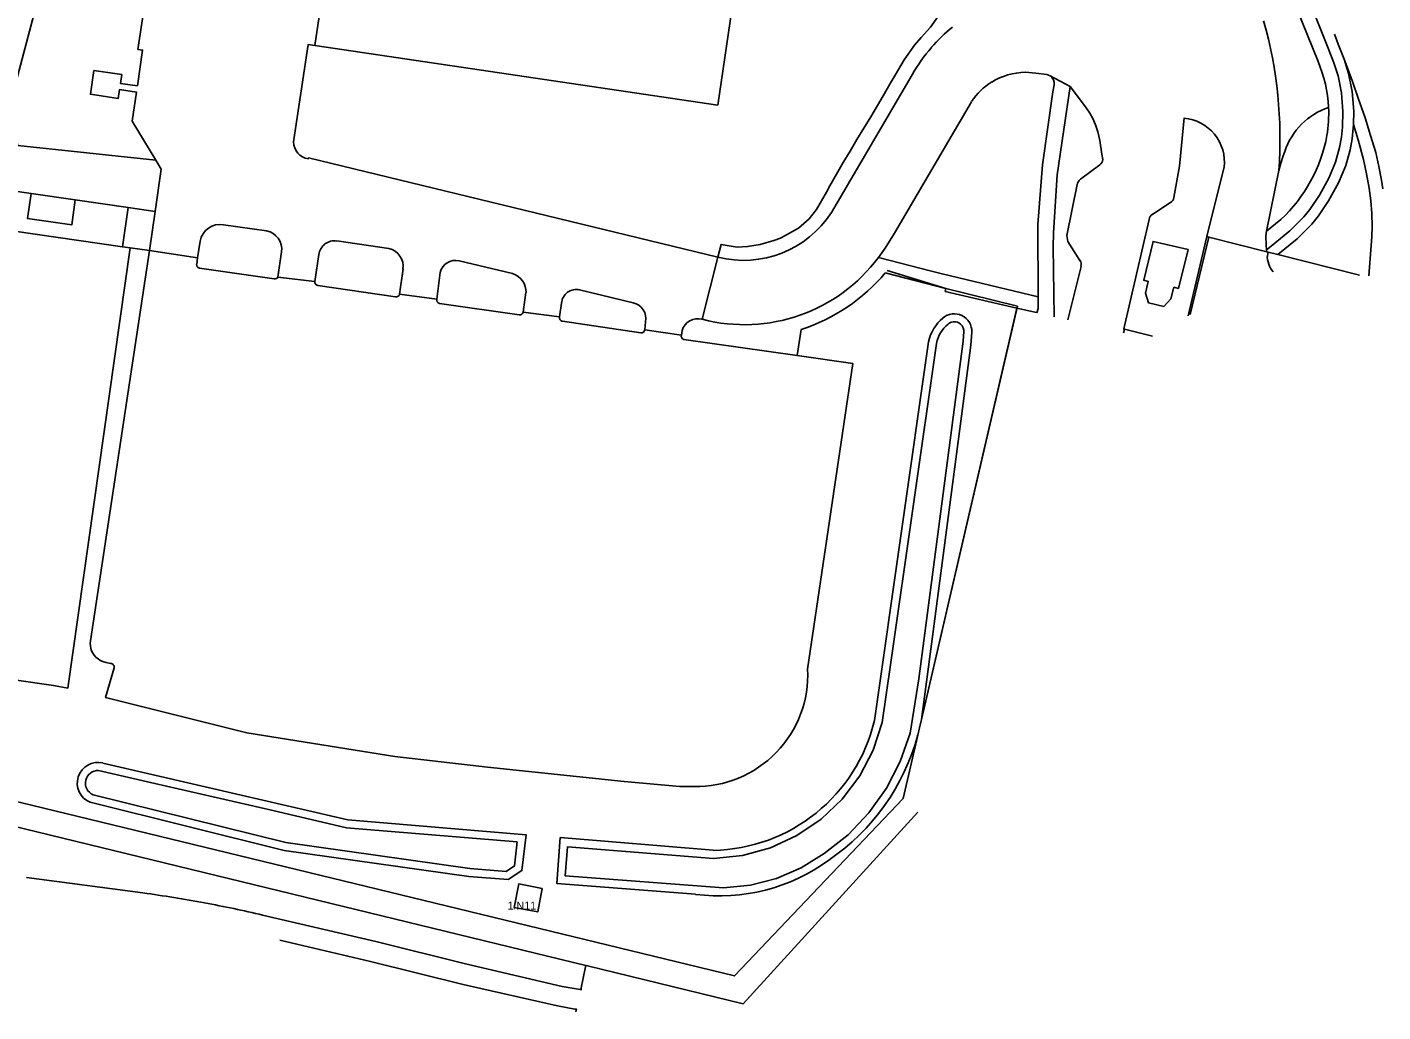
# Model space of a CAD drawing. Extents: x 163046 to 165074, y 382019 to 382874.
# Drawn here: x 164887 to 165056.4, y 382019.4 to 382142.4 of the extents above; entities that cross this region are included whole.
import ezdxf

# ---------------------------------------------------------------- set-up
doc = ezdxf.new("R2010")
doc.units = 0
for name, color, linetype in [('IMGEO_Berm_groen', 7, 'Continuous'), ('IMGEO_Erf', 7, 'Continuous'), ('IMGEO_Fietspad_gesloten', 7, 'Continuous'), ('IMGEO_Fietspad_open', 7, 'Continuous'), ('IMGEO_Groenvoorziening', 7, 'Continuous'), ('IMGEO_Hek', 7, 'Continuous'), ('IMGEO_Pand', 7, 'Continuous'), ('IMGEO_Pand_nummerreeks', 7, 'Continuous'), ('IMGEO_Parkeervlak_gesloten', 7, 'Continuous'), ('IMGEO_Parkeervlak_open', 7, 'Continuous'), ('IMGEO_Rijbaan_lokaal_gesloten', 7, 'Continuous'), ('IMGEO_Rijbaan_lokaal_open', 7, 'Continuous'), ('IMGEO_Voetpad_open', 7, 'Continuous'), ('IMGEO_Waterloop', 7, 'Continuous')]:
    doc.layers.add(name, color=color, linetype=linetype)

msp = doc.modelspace()

# ---------------------------------------------------------------- linework, layer by layer
at = {"layer": 'IMGEO_Berm_groen'}
msp.add_lwpolyline([(165043.31, 382114.01), (165053.48, 382111.43)], dxfattribs=at)
at = {"layer": 'IMGEO_Erf'}
msp.add_lwpolyline([(164899.25, 382173.36), (164895.44, 382168.42), (164892.95, 382163.15), (164891.24, 382156.72), (164887.33, 382141.95), (164884.69, 382132.02), (164885.86, 382127.64)], dxfattribs=at)
at = {"layer": 'IMGEO_Fietspad_gesloten'}
for points in [[(164901.48, 382034.26), (164886.96, 382036.16)], [(164956.22, 382022.18), (164956.12, 382022.19), (164953.88, 382022.57), (164941.81, 382025.37), (164930.58, 382028.18), (164916.45, 382031.48)], [(164918.61, 382028.36), (164929.91, 382025.67), (164941.52, 382022.81), (164953.3, 382020.13), (164955.47, 382019.72), (164955.65, 382019.7)], [(164956.32, 382022.17), (164956.22, 382022.18)], [(164955.72, 382019.69), (164955.65, 382019.7)]]:
    msp.add_lwpolyline(points, dxfattribs=at)
for centre, radius, start, end in [((164878.38, 381867.91), 167.94, 79.4249, 82.0936), ((164878.35, 381867.42), 168.43, 76.9252, 79.4441)]:
    msp.add_arc(centre, radius, start, end, dxfattribs=at)
at = {"layer": 'IMGEO_Fietspad_open'}
for points in [[(165041.88, 382114.6), (165042.46, 382115.06), (165044.81, 382116.97), (165046.53, 382118.72), (165047.31, 382119.67), (165048.49, 382121.44), (165049.66, 382123.56), (165050.51, 382125.59), (165051.01, 382127.42), (165051.24, 382128.68), (165051.37, 382129.96), (165051.43, 382131.91), (165051.26, 382134.23), (165050.83, 382136.34), (165050.31, 382138), (165049.6, 382139.82), (165045.28, 382150.62)], [(165043.62, 382149.82), (165048.32, 382138.13)], [(165015.34, 382135.25), (165015.2, 382134.35), (165013.87, 382125.23), (165013.3, 382117.77), (165013.35, 382108.72)], [(165015.34, 382106.26), (165015.24, 382115), (165015.25, 382116.74), (165015.73, 382124), (165017.36, 382135.02)], [(165043.68, 382118.41), (165041.88, 382116.94)], [(165013.2, 382106.76), (165013.36, 382107.28), (165013.35, 382108.72)]]:
    msp.add_lwpolyline(points, dxfattribs=at)
for centre, radius, start, end in [((165033.03, 382131.63), 16.62, 2.75, 23.0338), ((165014.19, 382135.38), 1.16, 353.1527, 56.2591), ((165032.96, 382131.62), 16.69, 350.5763, 2.7535), ((165030.58, 382132.41), 19.17, 313.1209, 349.4285)]:
    msp.add_arc(centre, radius, start, end, dxfattribs=at)
at = {"layer": 'IMGEO_Groenvoorziening'}
for points in [[(165005.06, 382104.33), (165004.93, 382102.71), (165000, 382065.32), (164998.76, 382055.9)], [(164992.89, 382055.79), (164999.66, 382103.13)], [(164896.49, 382050.48), (164927.09, 382043.38), (164949.37, 382041.52), (164948.84, 382037.04), (164947.13, 382035.91), (164942.23, 382036.3), (164919.16, 382039.55), (164894.91, 382045.57)], [(164970.53, 382034.07), (164953.19, 382035.44), (164953.64, 382041.16), (164972.76, 382039.57)]]:
    msp.add_lwpolyline(points, dxfattribs=at)
for centre, radius, start, end in [((165004.77, 382102.07), 5.22, 129.5656, 168.2281), ((165002.87, 382104.43), 2.19, 357.3821, 130.7763), ((164972.36, 382060.66), 21.1, 271.0694, 346.6392), ((164971.63, 382061.19), 27.64, 304.3023, 344.8961), ((164895.88, 382047.97), 2.59, 76.4768, 248.0161), ((164973.54, 382056.96), 23.09, 262.5139, 306.2932)]:
    msp.add_arc(centre, radius, start, end, dxfattribs=at)
at = {"layer": 'IMGEO_Hek'}
for points in [[(164548.87, 382121.27), (164552, 382120.52), (164561.05, 382119.57), (164562.96, 382119.37), (164565.36, 382119.11), (164598.77, 382115.22), (164621.38, 382109.91), (164648.88, 382103.16), (164975.4, 382023.88), (164996.47, 382046.06), (164998.31, 382053.98)], [(165041.9, 382114.37), (165034.66, 382116.21), (165032.36, 382106.54)], [(165042.1, 382114.32), (165041.9, 382114.37)], [(165043.31, 382114.01), (165042.1, 382114.32)], [(164957.04, 382025.14), (164956.85, 382025.19), (164602.85, 382111.38), (164599.99, 382112.07), (164598.73, 382112.35), (164598.36, 382112.35)], [(165010.75, 382107.57), (165001.81, 382109.8), (164994.49, 382112.04)], [(164998.76, 382055.9), (165010.75, 382107.57)], [(164998.31, 382053.98), (164998.52, 382054.86), (164998.76, 382055.9)], [(164998.3, 382044.35), (164976.47, 382020.39)]]:
    msp.add_lwpolyline(points, dxfattribs=at)
at = {"layer": 'IMGEO_Pand'}
for points in [[(164922.97, 382140.15), (164973.31, 382132.7), (164976.41, 382153.71)], [(164923.75, 382145.43), (164922.97, 382140.15)], [(165032.08, 382114.65), (165030.87, 382109.8), (165030.31, 382109.94), (165029.93, 382108.47), (165029.04, 382107.55), (165027.15, 382107.97), (165026.76, 382109.19), (165027.11, 382110.67), (165026.53, 382110.81), (165027.71, 382115.66), (165032.08, 382114.65)], [(164951.39, 382034.81), (164950.83, 382031.87), (164947.89, 382032.43), (164948.45, 382035.37), (164951.39, 382034.81)]]:
    msp.add_lwpolyline(points, dxfattribs=at)
at = {"layer": 'IMGEO_Parkeervlak_gesloten'}
msp.add_lwpolyline([(165044.16, 382126.92), (165043.96, 382126.35), (165043.67, 382125.44), (165043.41, 382124.53)], dxfattribs=at)
msp.add_arc((165052.53, 382124.07), 8.84, 109.1598, 161.2369, dxfattribs=at)
at = {"layer": 'IMGEO_Parkeervlak_open'}
for points in [[(164898.94, 382115), (164879.93, 382117.75)], [(164899.91, 382114.86), (164892.11, 382059.85), (164890.33, 382060.16), (164871.21, 382062.93)], [(164902.3, 382114.51), (164894.95, 382065.75)], [(164908.32, 382113.61), (164908.21, 382112.83)], [(164908.58, 382112.33), (164917.9, 382110.97)], [(164923.35, 382110.17), (164933.06, 382108.73)], [(164938.55, 382107.92), (164948.52, 382106.49)], [(164953.92, 382105.68), (164963.71, 382104.24)], [(164984.54, 382062.19), (164990.2, 382100.39), (164983.25, 382101.39)], [(164896.9, 382063.03), (164897.45, 382062.92)], [(164897.89, 382062.36), (164896.83, 382058.66), (164914.49, 382054.25), (164932.97, 382051.3), (164944.56, 382049.97), (164961.62, 382048.15), (164968.57, 382047.56), (164970.34, 382047.53)]]:
    msp.add_lwpolyline(points, dxfattribs=at)
for centre, radius, start, end in [((164908.64, 382112.77), 0.438, 171.3193, 261.6835), ((164917.97, 382111.37), 0.405, 259.0794, 335.6832), ((164923.4, 382110.6), 0.427, 169.758, 263.2449), ((164933.11, 382109.2), 0.473, 263.3412, 344.0389), ((164938.64, 382108.36), 0.447, 170.5053, 258.3116), ((164948.59, 382106.89), 0.401, 259.9073, 350.3244), ((164954, 382106.15), 0.475, 170.1555, 260.3452), ((164963.76, 382104.67), 0.431, 263.5405, 353.3973), ((164897.15, 382065.36), 2.24, 169.9106, 235.5071), ((164897.44, 382065.46), 2.49, 231.4441, 257.48), ((164897.42, 382062.45), 0.474, 349.5505, 86.6098), ((164970.57, 382061.52), 13.99, 269.0693, 2.7649)]:
    msp.add_arc(centre, radius, start, end, dxfattribs=at)
at = {"layer": 'IMGEO_Rijbaan_lokaal_gesloten'}
for points in [[(164997.6, 382136.5), (164987.51, 382119.26)], [(165011.73, 382136.8), (165013.05, 382136.69), (165014.44, 382136.52), (165014.83, 382136.35)], [(165017.36, 382135.02), (165014.83, 382136.35)], [(165021.41, 382125.9), (165021.32, 382126.55), (165021.07, 382128.28), (165020.82, 382129.36), (165020.51, 382130.25), (165020.17, 382131.02), (165019.79, 382131.71), (165019.36, 382132.37), (165018.89, 382133), (165017.36, 382135.02)], [(164993.4, 382113.66), (164994.22, 382114.81), (164995.4, 382116.69), (165005.03, 382133.13)], [(165031.58, 382131.09), (165031.01, 382125.09), (165030.31, 382121.14)], [(164885.86, 382127.64), (164903.11, 382125.8)], [(164903.11, 382125.8), (164903.79, 382124.68), (164903.02, 382119.41)], [(165018.64, 382123.43), (165021.04, 382125.24)], [(165034.44, 382116.27), (165034.65, 382117.16), (165036.6, 382124.93)], [(165041.88, 382116.94), (165043.41, 382124.53)], [(164882.62, 382122.36), (164887.54, 382121.65)], [(165018.57, 382113.3), (165017.07, 382115.64), (165016.92, 382116.41), (165018.22, 382122.77)], [(164887.54, 382121.65), (164893.04, 382120.85)], [(164893.04, 382120.85), (164899.65, 382119.9)], [(165029.89, 382120.52), (165028.19, 382119.41), (165027.63, 382119.05)], [(164899.65, 382119.9), (164903.02, 382119.41)], [(165027.2, 382118.42), (165024.04, 382104.72), (165024.12, 382104.7)], [(165041.88, 382116.94), (165041.8, 382116.35), (165041.82, 382115.21), (165041.88, 382114.6)], [(165034.44, 382116.27), (165032.08, 382106.38)], [(165041.9, 382114.37), (165034.66, 382116.21), (165034.44, 382116.27)], [(164973.33, 382113.68), (164971.38, 382105.93)], [(165041.88, 382114.6), (165041.9, 382114.37)], [(165042.1, 382114.32), (165041.9, 382114.37)], [(165042.71, 382111.85), (165042.54, 382112.08), (165042.39, 382112.32), (165042.26, 382112.57), (165042.15, 382112.84), (165042.07, 382113.11), (165042.01, 382113.39), (165041.97, 382113.67), (165042.1, 382114.32)], [(165017.06, 382105.85), (165018.7, 382112.55)], [(165024.12, 382104.7), (165024, 382104.22)]]:
    msp.add_lwpolyline(points, dxfattribs=at)
for centre, radius, start, end in [((165015.61, 382126.39), 20.65, 128.9397, 139.1131), ((164990.66, 382128.62), 52.9, 355.5693, 16.0146), ((165015.7, 382126.31), 20.76, 139.1141, 150.6292), ((165011.79, 382128.72), 8.08, 121.7268, 146.8426), ((165011.93, 382128.25), 8.55, 91.3486, 120.8889), ((165031.05, 382125.53), 5.58, 353.7795, 84.4866), ((165020.51, 382125.97), 0.906, 305.9775, 355.414), ((165019.34, 382122.52), 1.15, 127.5782, 167.4794), ((165029.48, 382121.25), 0.837, 299.2947, 352.4764), ((164976.5, 382126.47), 13.17, 256.0936, 326.8054), ((165028.17, 382118.22), 0.992, 123.065, 168.3048), ((164976.64, 382126.18), 20.92, 255.4419, 323.2431), ((165017.7, 382112.78), 1.02, 347.2663, 31.0632)]:
    msp.add_arc(centre, radius, start, end, dxfattribs=at)
at = {"layer": 'IMGEO_Rijbaan_lokaal_open'}
for points in [[(164903.4, 382158.01), (164903.55, 382159.66), (164892.91, 382161.18), (164890.74, 382146.43), (164901.63, 382144.87), (164900.87, 382139.65), (164901.46, 382139.57), (164900.81, 382135.11), (164898.68, 382135.42), (164898.84, 382136.51), (164895.38, 382137.02), (164894.94, 382134.05), (164898.4, 382133.54), (164898.56, 382134.63), (164900.69, 382134.32), (164900.16, 382130.69), (164903.11, 382125.8)], [(164920.32, 382128.1), (164922.13, 382140.26), (164922.97, 382140.15)], [(164973.33, 382113.68), (164922.16, 382126.1), (164922.13, 382125.97)], [(164903.02, 382119.41), (164902.3, 382114.51)], [(164911.57, 382117.74), (164916.93, 382116.98)], [(164908.32, 382113.61), (164908.64, 382115.69)], [(164925.71, 382115.72), (164932.23, 382114.78)], [(164902.3, 382114.51), (164908.32, 382113.61)], [(164918.8, 382114.35), (164918.34, 382111.21)], [(164922.98, 382110.67), (164923.48, 382114.02)], [(164933.99, 382112.22), (164933.57, 382109.07)], [(164940.99, 382113.23), (164947.67, 382111.65)], [(164918.34, 382111.21), (164922.98, 382110.67)], [(164938.2, 382108.43), (164938.64, 382111.8)], [(164933.57, 382109.07), (164938.2, 382108.43)], [(164949.35, 382109.27), (164948.99, 382106.82)], [(164956.06, 382109.6), (164962.74, 382108.01)], [(164948.99, 382106.82), (164953.53, 382106.23)], [(164953.53, 382106.23), (164953.8, 382107.93)], [(164964.3, 382105.62), (164964.19, 382104.62)], [(164964.19, 382104.62), (164968.77, 382103.95)], [(164968.85, 382104.53), (164968.77, 382103.95)]]:
    msp.add_lwpolyline(points, dxfattribs=at)
for centre, radius, start, end in [((164922.5, 382128.12), 2.18, 180.633, 260.3961), ((164911.14, 382115.24), 2.55, 80.3337, 169.6319), ((164916.51, 382114.71), 2.32, 351.0322, 79.6107), ((164925.4, 382113.82), 1.92, 80.681, 174.2919), ((164931.73, 382112.55), 2.28, 351.5603, 77.3941), ((164940.54, 382111.34), 1.95, 76.5139, 166.4855), ((164947.01, 382109.39), 2.35, 356.8616, 73.5736), ((164955.63, 382107.83), 1.83, 76.2136, 176.6536), ((164962.28, 382106), 2.06, 349.5399, 76.9805), ((164970.83, 382103.95), 2.06, 74.5983, 163.6839)]:
    msp.add_arc(centre, radius, start, end, dxfattribs=at)
at = {"layer": 'IMGEO_Voetpad_open'}
for points in [[(165000.83, 382143.74), (164999.89, 382142.43), (164998.73, 382141.13), (164997.9, 382140.21), (164996.62, 382138.35), (164995.47, 382136.43), (164994.98, 382135.59), (164994.14, 382134.14), (164993.7, 382133.38), (164992.44, 382131.25), (164991.57, 382129.82), (164990.71, 382128.4), (164989.84, 382126.96), (164988.98, 382125.52), (164988.14, 382124.07), (164987.31, 382122.6), (164986.89, 382121.82), (164985.65, 382119.65), (164984.75, 382118.49), (164983.39, 382117.33), (164981.17, 382116.07), (164980.34, 382115.76), (164978.6, 382115.3), (164977.05, 382115.01), (164975.75, 382114.94), (164973.73, 382115.29), (164973.33, 382113.68)], [(165051.59, 382138.45), (165050.85, 382140.31), (165050.36, 382141.55)], [(165056.42, 382122.25), (165056.25, 382123.3), (165055.9, 382125.02), (165055.52, 382126.76), (165054.89, 382128.9), (165054.21, 382131.1), (165053.35, 382133.56), (165052.62, 382135.63), (165051.59, 382138.45)], [(165051.59, 382138.45), (165052.14, 382136.67), (165052.6, 382134.42), (165052.78, 382131.94), (165052.73, 382130.26)], [(165052.73, 382130.26), (165052.72, 382129.87), (165052.58, 382128.49), (165052.33, 382127.12), (165051.79, 382125.15), (165050.88, 382122.97), (165049.64, 382120.74), (165048.39, 382118.87), (165047.54, 382117.82), (165045.72, 382115.97), (165043.31, 382114.01)], [(165054.68, 382111.38), (165055.04, 382116.24), (165055.09, 382117.53), (165055.05, 382119.17), (165054.92, 382120.74), (165054.7, 382122.33), (165054.38, 382124.11), (165053.98, 382125.91), (165053.33, 382128.34), (165052.73, 382130.26)], [(164998.31, 382053.98), (164996.47, 382046.06), (164975.4, 382023.88), (164648.88, 382103.16), (164621.38, 382109.91), (164598.77, 382115.22), (164565.36, 382119.11), (164562.96, 382119.37), (164561.05, 382119.57), (164552, 382120.52), (164548.87, 382121.27)], [(164887.54, 382121.65), (164887.09, 382118.51), (164892.59, 382117.73), (164893.04, 382120.85)], [(164899.65, 382119.9), (164898.94, 382115)], [(164899.91, 382114.86), (164898.94, 382115)], [(164902.3, 382114.51), (164899.91, 382114.86)], [(165013.35, 382108.72), (165001.35, 382111.6), (165000, 382111.95), (164993.4, 382113.66)], [(165042.1, 382114.32), (165043.31, 382114.01)], [(164956.85, 382025.19), (164602.85, 382111.38), (164599.99, 382112.07), (164598.73, 382112.35), (164592.38, 382113.1)], [(164994.24, 382111.74), (165001.81, 382109.8), (165001.73, 382109.42), (165010.7, 382107.34)], [(165010.7, 382107.34), (164998.76, 382055.9)], [(165010.7, 382107.34), (165013.15, 382106.77)], [(164969.08, 382103.42), (164983.25, 382101.39)], [(164983.25, 382101.39), (164983.74, 382104.65)], [(165027.62, 382103.84), (165024.12, 382104.7)], [(164998.76, 382055.9), (164998.52, 382054.86), (164998.31, 382053.98)], [(164998.3, 382044.35), (164976.47, 382020.39)], [(164956.85, 382025.19), (164956.8, 382025), (164956.22, 382022.18)], [(164976.47, 382020.39), (164957.04, 382025.14), (164956.85, 382025.19)], [(164955.65, 382019.7), (164955.57, 382019.38)]]:
    msp.add_lwpolyline(points, dxfattribs=at)
for centre, radius, start, end in [((164976.53, 382126.66), 23.16, 288.1257, 319.8962), ((164969.18, 382103.84), 0.426, 165.519, 255.7582)]:
    msp.add_arc(centre, radius, start, end, dxfattribs=at)
at = {"layer": 'IMGEO_Waterloop'}
for points in [[(165003.97, 382103.22), (165004.02, 382103.84), (165004.06, 382104.35), (165004.05, 382104.58)], [(165000.64, 382102.92), (164994.9, 382062.75), (164993.87, 382055.56), (164992.74, 382052.1), (164991.06, 382048.87), (164988.87, 382045.96), (164986.23, 382043.45), (164983.21, 382041.41), (164979.91, 382039.89), (164976.39, 382038.93), (164972.77, 382038.56), (164954.55, 382039.99), (164954.27, 382036.36), (164974.04, 382034.89), (164977.39, 382035.22), (164980.65, 382036.05), (164983.75, 382037.38), (164986.63, 382039.17), (164989.6, 382041.52), (164992.2, 382044.26), (164994.38, 382047.33), (164996.11, 382050.68), (164997.34, 382054.23), (164998.42, 382060.98), (165003.97, 382103.22)], [(164948.26, 382040.61), (164926.93, 382042.39), (164917.54, 382044.57), (164903, 382047.94), (164895.96, 382049.54)], [(164895.26, 382046.51), (164919.35, 382040.54), (164942.34, 382037.29), (164946.87, 382036.94), (164947.9, 382037.62), (164948.26, 382040.61)]]:
    msp.add_lwpolyline(points, dxfattribs=at)
for centre, radius, start, end in [((165004.78, 382102.06), 4.23, 129.4684, 168.3103), ((165002.87, 382104.44), 1.18, 62.2937, 131.2964), ((165002.96, 382104.49), 1.09, 4.525, 65.1017), ((164895.88, 382047.97), 1.58, 87.1022, 247.1571)]:
    msp.add_arc(centre, radius, start, end, dxfattribs=at)

# ---------------------------------------------------------------- texts
at = {"layer": 'IMGEO_Pand_nummerreeks'}
msp.add_text('1/N11', height=1, dxfattribs=at).set_placement((164947.05, 382032.15))

doc.saveas('drawing.dxf')
